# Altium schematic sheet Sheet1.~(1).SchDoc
size A4; SheetNumber: 1; SheetTotal: 1
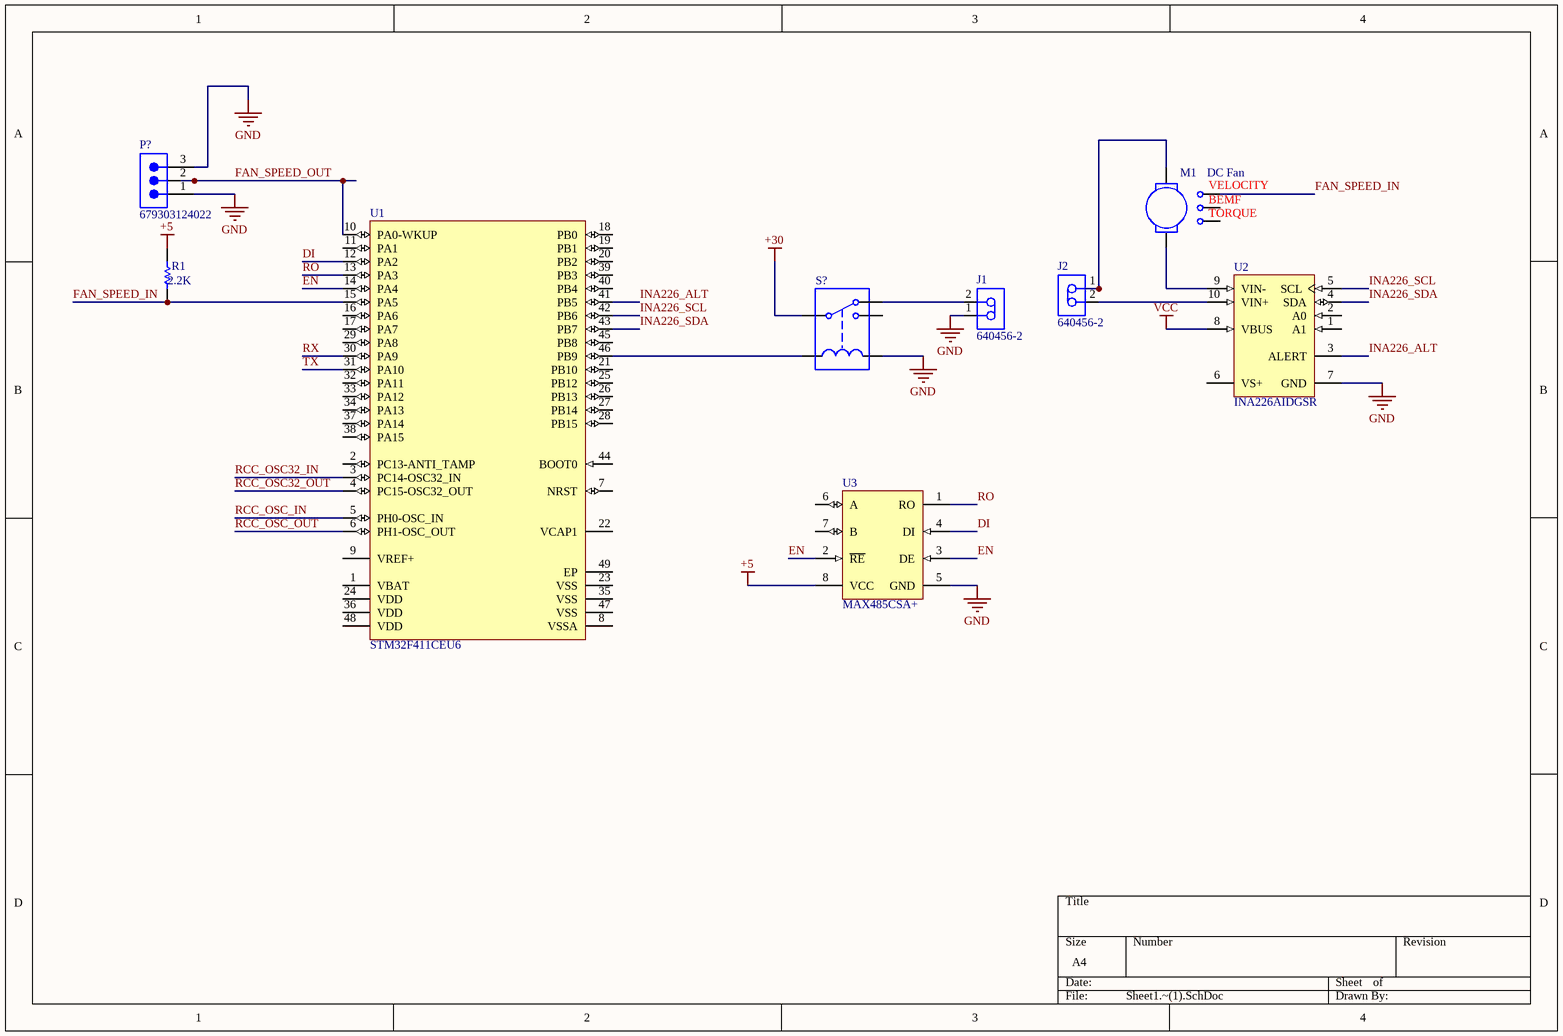
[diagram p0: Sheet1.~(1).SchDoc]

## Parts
J1  640456-2  [TECO-640456-2_V]
J2  640456-2  [TECO-640456-2_V]
M1  DC Fan
P?  679303124022  [679303124022]
R1  value 2.2K  (hidden comment: Resistor)
S?  Single-Pole, Double-Throw Relay  (value not drawn)
U1  STM32F411CEU6  [STM-UFQFPN48_L]
U2  INA226AIDGSR  [DGS0010A_L]
U3  MAX485CSA+  [MAXM-MAX485CSA+-8_M]

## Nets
+5: R1.2 U3.8(VCC)
+30: S?.1
GND: J1.1 P?.1 P?.3 S?.5 U2.7(GND) U3.5(GND)
VCC: U2.8(VBUS)
DI: U1.12(PA2) U3.4(DI)
EN: U1.14(PA4) U3.2(~{RE}) U3.3(DE)
FAN_SPEED_IN: M1.3 R1.1 U1.15(PA5)
FAN_SPEED_OUT: P?.2 U1.10(PA0-WKUP)
INA226_ALT: U1.41(PB5) U2.3(ALERT)
INA226_SCL: U1.42(PB6) U2.5(SCL)
INA226_SDA: U1.43(PB7) U2.4(SDA)
RCC_OSC32_IN: U1.3(PC14-OSC32_IN)
RCC_OSC32_OUT: U1.4(PC15-OSC32_OUT)
RCC_OSC_IN: U1.5(PH0-OSC_IN)
RCC_OSC_OUT: U1.6(PH1-OSC_OUT)
RO: U1.13(PA3) U3.1(RO)
RX: U1.30(PA9)
TX: U1.31(PA10)
NetJ1_2: J1.2 S?.3
NetJ2_1: J2.1 M1.1
NetJ2_2: J2.2 U2.10(VIN+)
NetM1_2: M1.2 U2.9(VIN-)
NetS?_4: S?.4 U1.46(PB9)

Not connected (* = marked no-connect by the designer): M1 4 5; S? 2; U1 1(VBAT) 2(PC13-ANTI_TAMP) 7(NRST) 8(VSSA) 9(VREF+) 11(PA1) 16(PA6) 17(PA7) 18(PB0) 19(PB1) 20(PB2) 21(PB10) 22(VCAP1) 23(VSS) 24(VDD) 25(PB12) 26(PB13) 27(PB14) 28(PB15) 29(PA8) 32(PA11) 33(PA12) 34(PA13) 35(VSS) 36(VDD) 37(PA14) 38(PA15) 39(PB3) 40(PB4) 44(BOOT0) 45(PB8) 47(VSS) 48(VDD) 49(EP); U2 1(A1) 2(A0) 6(VS+); U3 6(A) 7(B)

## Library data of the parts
J1 J2 = CMP-2000-05417-1: Male Header, Pitch 2.54 mm, 1 x 2 Position, Height 10.49 mm, Tail Length 3.556 mm, -55 to 105 degC, RoHS, Bulk; Manufacturer: TE Connectivity; Standards: RoHSCompliant,ELVCompliant,UL94V-0; Material, Housing: Polyester; Agency Approvals: CSA,UL; Brand/Series: MTA-100Series; Contact Centerline Spacing: 0.100 / in.; Material, Contact: CopperAlloy; Current, Rating: 5 / A; Color, Housing: White; Contact Termination Area Plating: Tin; Special Features: Pinstrip; Number of Positions: 2; Pin Spacing: 0.1 / "; Temperature, Operating: -55to+105 / degC; Angle: Straight; Mount Angle: Vertical; Connector Type: MTA-100; Primary Type: InterconnectSystem; Voltage, Rating: 250 / V; Mounting Hole Size: 0.04 / "
M1 = DC Motor: LA: 1.5M; RA: 0.5; KE: 0.05; JM: 250U; BM: 0.1M; TL: 0; SimulationGenericComponent: True
P? = CMP-1502-00722-2: NexarPartId: 18818282; Insulation: Insulated; Operating Supply Voltage: 50V; Number of Contacts: 3; Current Rating: 1A; Insulation Resistance: 100MΩ; Gender: Male; Contact Resistance: 20mΩ; Connector Type: Male Pin; Pitch: 1.5mm
R1 = Resistor: TC1: 0; SimulationGenericComponent: True
S? = SPDT Relay: L_C: 1u; R_C: 100; RON: 1; ROFF: 1e12; ION: 1m; IOFF: 0; SimulationGenericComponent: True
U1 = CMP-0243-00165-1: ARM Cortex-M4 32-bit MCU+FPU, 512 KB Flash, 128 KB RAM, 36 I/Os, 48-Pin UFQFPN, -40 to 85 degC, Tray; Operating Frequency(F) (Processor speed) (MHz): 100; FLASH Size (Prog) (kB): 512; Internal RAM Size (kB): 128; I/Os (High Current): 36; Supply Voltage(Vcc) min (V): 1.7
U2 = CMP-0704-00058-2: High-Side Measurement, Bi-Directional Current / Power Monitor with I2C Interface, 2.7 to 5.5 V, -40 to 125 degC, 10-pin SOP (DGS10), Green (RoHS & no Sb/Br); Vs(Max)(V): 5.5; CMRR(Min)(dB): 126; Rating: Catalog; Input Offset (+/-)(Max)(uV): 10; Small-Signal Bandwidth(Typ)(MHz): 0.007; Input Offset Drift (+/-)(Max)(uV/Degrees Celsius): 0.1; Common Mode Range(Max)(V): 36; Gain(V/V): 1; SubFamily: Current Shunt Monitor; Quiescent Current (+/-)(Typ)(mA): 0.33; Vs(Min)(V): 2.7; Common Mode Range(Min)(V): 0
U3 = CMP-2000-05211-1: Low-Power, Slew-Rate-Limited RS-485/RS-422 Transceiver, 4.75 to 5.25 V, 0 to 70 degC, 8-Pin SOIC, RoHS, Tape and Reel; Manufacturer: Maxim; No. of Receivers: 1; Transceiver Type: Differential; Supply Voltage Min: 4.75V; IC Generic Number: 485; IC Temperature Range: Commercial; No. of Pins: 8; Supply Voltage Range: 4.75Vto5.25V; Interface: RS-422/RS-485; Supply Voltage Max: 5.25V; Data Rate: 2.5Mbps; Line / Bus Driver / Receiver / Transceiver Type: CMOSDifferential; Supply Current: 500µA; Interface Type: RS422,RS485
